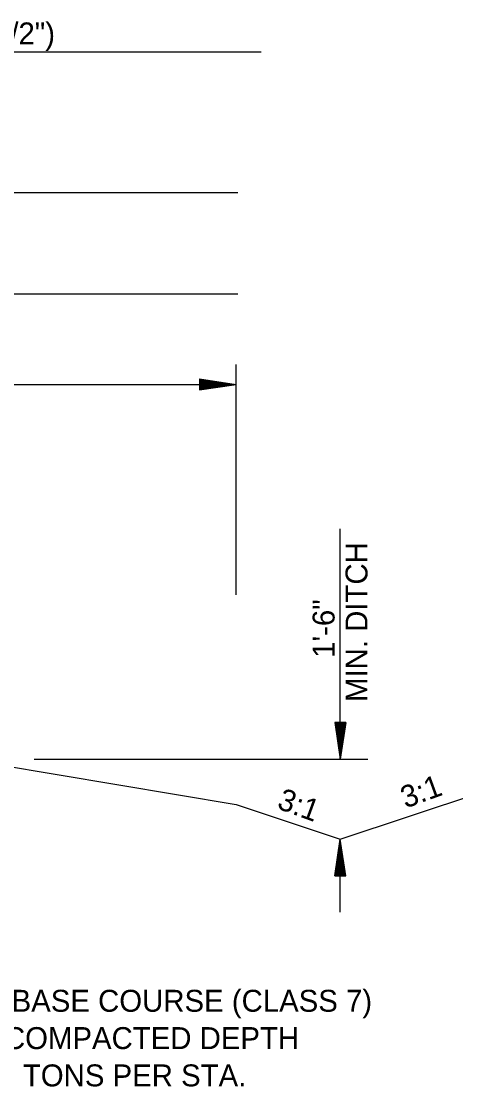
# Model space of a CAD drawing. Extents: x 1371763 to 1372860, y 385599 to 385872.
# Drawn here: x 1372390.7 to 1372402.58, y 385658.05 to 385687.17 of the extents above; entities that cross this region are included whole.
import ezdxf

# ---------------------------------------------------------------- set-up
doc = ezdxf.new("R2010")
doc.units = 0
doc.layers.add('R_Draft', color=7, linetype='Continuous')
doc.layers.add('R_Fin Surface', color=7, linetype='Continuous')

msp = doc.modelspace()

# ---------------------------------------------------------------- linework, layer by layer
at = {"layer": 'R_Draft'}
for p, q in [((1372397.255, 385686.33), (1372371.579, 385686.33)), ((1372396.621, 385682.486), (1372371.579, 385682.486)), ((1372396.621, 385679.71), (1372371.579, 385679.71)), ((1372396.577, 385671.49), (1372396.577, 385677.788)), ((1372372.578, 385677.247), (1372396.577, 385677.247)), ((1372395.577, 385677.397), (1372396.577, 385677.247)), ((1372395.577, 385677.397), (1372395.577, 385677.097)), ((1372395.577, 385677.372), (1372396.41, 385677.247)), ((1372395.577, 385677.347), (1372396.238, 385677.247)), ((1372395.577, 385677.322), (1372396.071, 385677.247)), ((1372395.577, 385677.296), (1372395.902, 385677.247)), ((1372395.577, 385677.271), (1372395.735, 385677.247)), ((1372395.577, 385677.097), (1372396.577, 385677.247)), ((1372395.577, 385677.198), (1372395.902, 385677.247)), ((1372395.577, 385677.148), (1372396.238, 385677.247)), ((1372395.577, 385677.122), (1372396.41, 385677.247)), ((1372395.577, 385677.173), (1372396.071, 385677.247)), ((1372395.577, 385677.224), (1372395.735, 385677.247)), ((1372399.423, 385667.001), (1372399.423, 385673.3)), ((1372380.577, 385668.43), (1372396.577, 385665.763)), ((1372399.273, 385668.001), (1372399.423, 385667.001)), ((1372399.573, 385668.001), (1372399.273, 385668.001)), ((1372399.298, 385668.001), (1372399.423, 385667.168)), ((1372399.323, 385668.001), (1372399.423, 385667.34)), ((1372399.348, 385668.001), (1372399.423, 385667.507)), ((1372399.374, 385668.001), (1372399.423, 385667.676)), ((1372399.399, 385668.001), (1372399.423, 385667.843)), ((1372399.573, 385668.001), (1372399.423, 385667.001)), ((1372399.471, 385668.001), (1372399.423, 385667.676)), ((1372399.522, 385668.001), (1372399.423, 385667.34)), ((1372399.548, 385668.001), (1372399.423, 385667.168)), ((1372399.497, 385668.001), (1372399.423, 385667.507)), ((1372399.446, 385668.001), (1372399.423, 385667.843)), ((1372391.059, 385667.001), (1372400.173, 385667.001)), ((1372399.273, 385663.814), (1372399.423, 385664.814)), ((1372399.573, 385663.814), (1372399.423, 385664.814)), ((1372399.423, 385662.814), (1372399.423, 385664.814)), ((1372399.298, 385663.814), (1372399.423, 385664.647)), ((1372399.323, 385663.814), (1372399.423, 385664.475)), ((1372399.548, 385663.814), (1372399.423, 385664.647)), ((1372399.522, 385663.814), (1372399.423, 385664.475)), ((1372399.348, 385663.814), (1372399.423, 385664.309)), ((1372399.374, 385663.814), (1372399.423, 385664.139)), ((1372399.497, 385663.814), (1372399.423, 385664.309)), ((1372399.472, 385663.814), (1372399.423, 385664.139)), ((1372399.399, 385663.814), (1372399.423, 385663.972)), ((1372399.446, 385663.814), (1372399.423, 385663.972)), ((1372399.273, 385663.814), (1372399.573, 385663.814))]:
    msp.add_line(p, q, dxfattribs=at)
at = {"layer": 'R_Fin Surface'}
for p, q in [((1372399.423, 385664.814), (1372404.166, 385666.395)), ((1372396.577, 385665.763), (1372399.423, 385664.814))]:
    msp.add_line(p, q, dxfattribs=at)

# ---------------------------------------------------------------- texts
at = {"layer": 'R_Draft'}
for s, rotation, p in [('3\'-1 1/2" ACHM SURFACE COURSE (1/2")', 0, (1372376.233, 385686.54)), ('MIN. DITCH', 90, (1372400.166, 385668.564)), ('1\'-6"', 90, (1372399.266, 385669.771)), ('3:1', 19.9978, (1372401.206, 385665.648)), ('3:1', 340.0022, (1372397.665, 385665.661)), ('AGGREGATE BASE COURSE (CLASS 7)', 360, (1372385.133, 385660.094)), ('VAR. COMPACTED DEPTH', 360, (1372388.133, 385659.074)), ('99.75 TONS PER STA.', 360, (1372388.515, 385658.054))]:
    msp.add_text(s, height=0.6, rotation=rotation, dxfattribs=at).set_placement(p)

doc.saveas('drawing.dxf')
